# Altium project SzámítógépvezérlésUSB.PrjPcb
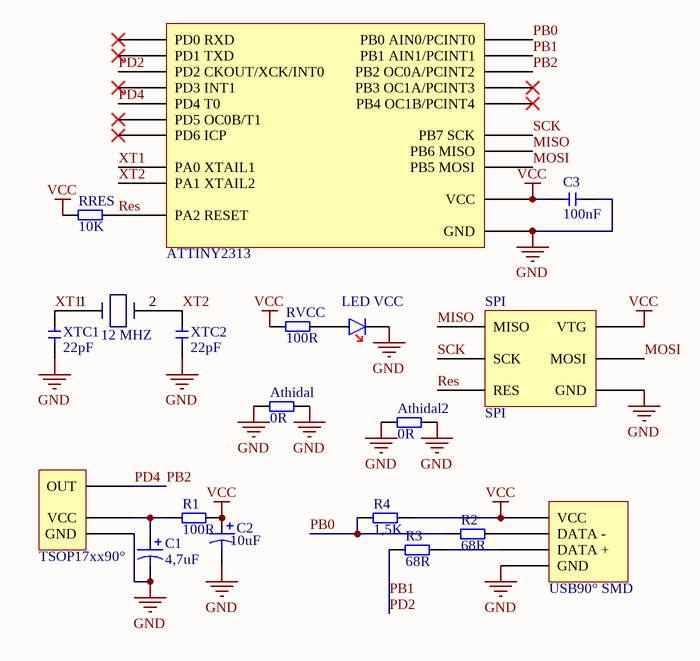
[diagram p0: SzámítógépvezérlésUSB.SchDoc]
1 sheet, 19 parts. Net scope: global (net labels, ports and power ports of the same name join across sheets).
Board file: SzámítógépvezérlésUSB.PcbDoc

## Sheet SzámítógépvezérlésUSB.SchDoc
size A4

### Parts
12_MHZ  12 MHZ  [Quartz]
Athidal  value 0R  [SM 3216[1206]]  (hidden comment: Res)
Athidal2  value 0R  [SM 3216[1206]]  (hidden comment: Res)
ATTINY2313  ATTINY2313  [ATTINY2313]  (value not drawn)
C1  value 4,7uF  [CAPPR5-5x5]  (hidden comment: Cap Pol1)
C2  value 10uF  [CAPPR5-5x5]  (hidden comment: Cap Pol1)
C3  value 100nF  [SM 3216[1206]]  (hidden comment: Cap)
LED_VCC  LED  [SM 3216[1206] - pol]  (value not drawn)
R1  value 100R  [SM 3216[1206]]  (hidden comment: Res)
R2  value 68R  [SM 3216[1206]]  (hidden comment: Res)
R3  value 68R  [SM 3216[1206]]  (hidden comment: Res)
R4  value 1,5K  [SM 3216[1206]]  (hidden comment: Res)
RRES  value 10K  [SM 3216[1206]]  (hidden comment: Res)
RVCC  value 100R  [SM 3216[1206]]  (hidden comment: Res)
SPI  SPI  [SPI]  (value not drawn)
TSOP17xx90°  TSOP17xx90°  [TSOP17xx90°]  (value not drawn)
USB90°_SMD  USB90° SMD  [USB90° SMD]  (value not drawn)
XTC1  value 22pF  [SM 3216[1206]]  (hidden comment: Cap)
XTC2  value 22pF  [SM 3216[1206]]  (hidden comment: Cap)

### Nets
GND: Athidal.1 Athidal.2 Athidal2.1 Athidal2.2 ATTINY2313.10(GND) C1.2 C2.2 C3.2 LED_VCC.2(katód) SPI.6(GND) TSOP17xx90°.1(GND) USB90°_SMD.4(GND) XTC1.2 XTC2.2
VCC: ATTINY2313.20(VCC) C2.1 C3.1 R1.2 R4.1 RRES.1 RVCC.1 SPI.2(VTG) USB90°_SMD.1(VCC)
MISO: ATTINY2313.18(PB6_MISO) SPI.1(MISO)
MOSI: ATTINY2313.17(PB5_MOSI) SPI.4(MOSI)
PB0: ATTINY2313.12(PB0_AIN0/PCINT0) R2.1 R4.2
PB1: ATTINY2313.6(PD2_CKOUT/XCK/INT0) ATTINY2313.13(PB1_AIN1/PCINT1) R3.1  [also labelled PD2]
PB2: ATTINY2313.8(PD4_T0) ATTINY2313.14(PB2_OC0A/PCINT2) TSOP17xx90°.3(OUT)  [also labelled PD4]
Res: ATTINY2313.1(PA2_RESET) RRES.2 SPI.5(RES)
SCK: ATTINY2313.19(PB7_SCK) SPI.3(SCK)
XT1: 12_MHZ.1 ATTINY2313.5(PA0_XTAIL1) XTC1.1
XT2: 12_MHZ.2 ATTINY2313.4(PA1_XTAIL2) XTC2.1
NetC1_1: C1.1 R1.1 TSOP17xx90°.2(VCC)
NetLED_VCC_1: LED_VCC.1(anód) RVCC.2
NetR2_2: R2.2 USB90°_SMD.2(DATA_-)
NetR3_2: R3.2 USB90°_SMD.3(DATA_+)

Not connected (* = marked no-connect by the designer): ATTINY2313 2(PD0_RXD)* 3(PD1_TXD)* 7(PD3_INT1)* 9(PD5_OC0B/T1)* 11(PD6_ICP)* 15(PB3_OC1A/PCINT3)* 16(PB4_OC1B/PCINT4)*

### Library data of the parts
12_MHZ = Quartz: SMD
Athidal Athidal2 R1-R4 RRES RVCC = Res: Resistor
C1 C2 = Cap Pol1: Polarized Capacitor (Radial)
C3 XTC1 XTC2 = Cap: Capacitor
SPI = SPI: pin to pad: 1>2 2>1 3>4 4>3 5>6 6>5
